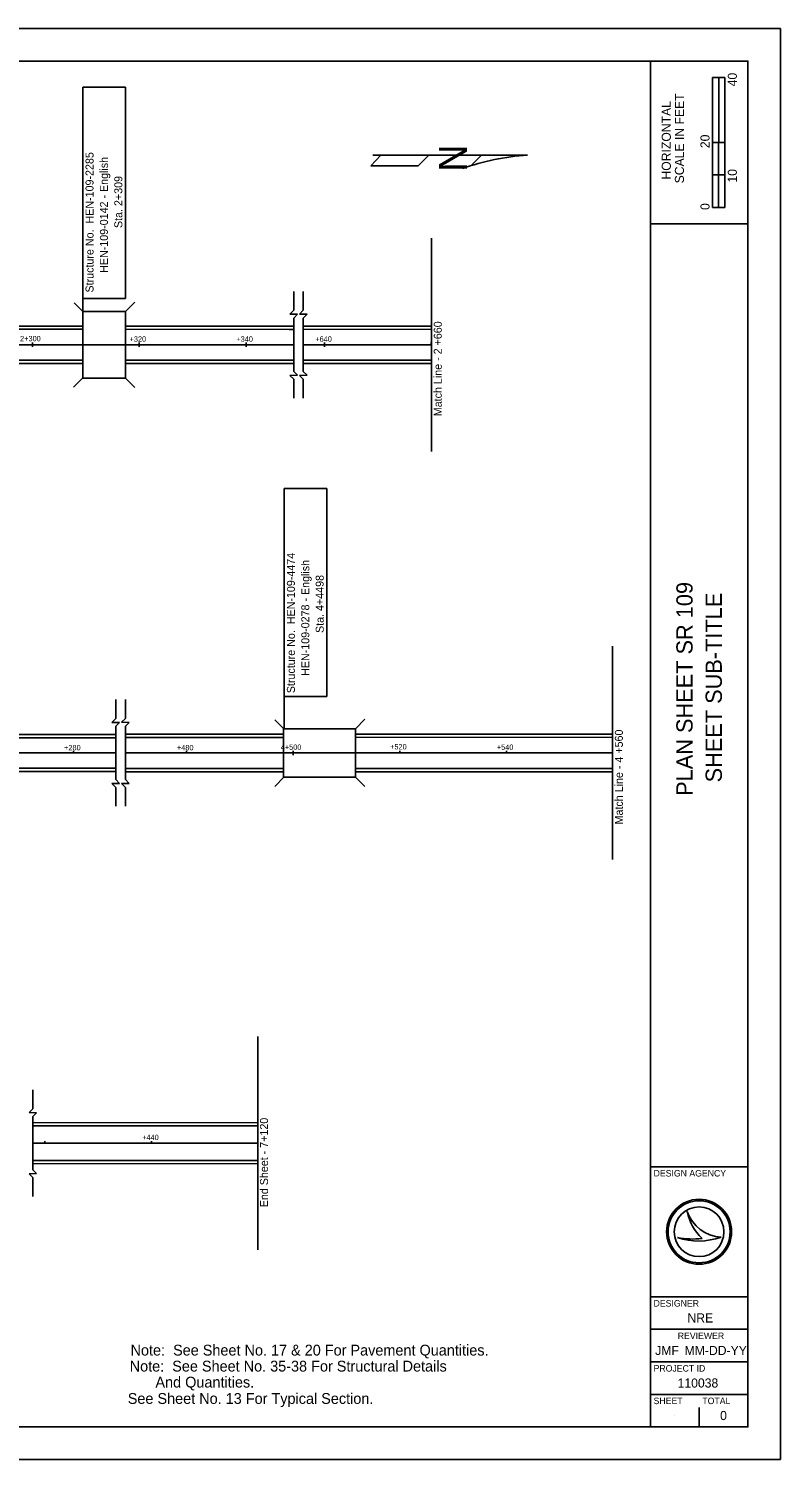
# Model space of a CAD drawing. Extents: x 3 to 683, y -6 to 434.
# Drawn here: x 451.7 to 682.9, y -6.3 to 433.7 of the extents above; entities that cross this region are included whole.
import ezdxf

# ---------------------------------------------------------------- set-up
doc = ezdxf.new("R2010")
doc.units = 0
for name, color, linetype in [('Default', 7, 'Continuous'), ('SH_Border', 7, 'Continuous'), ('SH_Cut_Line', 7, 'Continuous'), ('SH_Data', 7, 'Continuous')]:
    doc.layers.add(name, color=color, linetype=linetype)

msp = doc.modelspace()

# ---------------------------------------------------------------- linework, layer by layer
at = {"layer": 'Default'}
for p, q in [((468.32, 346.75), (468.32, 415.76)), ((468.32, 415.76), (481.45, 415.76)), ((481.48, 350.74), (481.43, 415.76)), ((559.96, 394.79), (556.87, 391.52)), ((557.56, 394.79), (605.01, 394.79)), ((574.75, 394.79), (571.48, 391.52)), ((590.91, 394.79), (587.65, 391.52)), ((571.48, 391.52), (556.87, 391.52)), ((575.55, 336.5), (575.55, 369.31)), ((533.22, 347.1), (533.22, 352.9)), ((536.13, 347.1), (536.13, 352.9)), ((465.67, 349.44), (468.57, 346.54)), ((468.34, 350.74), (481.46, 350.74)), ((481.45, 346.75), (484.35, 349.65)), ((468.32, 326.25), (468.32, 346.75)), ((481.45, 346.75), (468.32, 346.75)), ((481.45, 326.25), (481.45, 346.75)), ((532.03, 345.91), (533.22, 347.1)), ((532.03, 345.91), (534.38, 345.87)), ((533.22, 344.71), (534.38, 345.87)), ((533.22, 336.5), (533.22, 344.71)), ((534.95, 345.91), (536.13, 347.1)), ((534.95, 345.91), (537.29, 345.87)), ((536.13, 344.71), (537.29, 345.87)), ((536.13, 336.5), (536.13, 344.71)), ((468.32, 342.25), (414.87, 342.25)), ((468.32, 341.25), (414.87, 341.25)), ((532.92, 342.24), (481.45, 342.25)), ((532.92, 341.24), (481.45, 341.25)), ((533.22, 342.24), (531.8, 342.24)), ((533.22, 341.24), (531.8, 341.24)), ((575.55, 342.24), (536.13, 342.25)), ((575.55, 341.24), (536.13, 341.25)), ((532.92, 336.5), (414.87, 336.5)), ((452.9, 336.5), (452.9, 337.15)), ((452.9, 336.5), (452.9, 335.84)), ((485.71, 336.5), (485.71, 337.15)), ((485.71, 336.5), (485.71, 335.84)), ((518.52, 336.5), (518.52, 337.15)), ((518.52, 336.5), (518.52, 335.84)), ((533.22, 336.5), (531.8, 336.5)), ((533.22, 336.5), (533.22, 328.29)), ((575.55, 336.5), (536.13, 336.5)), ((536.13, 336.5), (536.13, 328.29)), ((542.71, 336.5), (542.71, 337.15)), ((542.71, 336.5), (542.71, 335.84)), ((575.52, 336.5), (575.52, 337.15)), ((575.55, 336.51), (575.55, 303.7)), ((468.32, 331.75), (414.87, 331.75)), ((468.32, 330.75), (414.87, 330.75)), ((532.92, 331.75), (481.45, 331.75)), ((532.92, 330.75), (481.45, 330.75)), ((533.22, 331.75), (531.8, 331.75)), ((533.22, 330.75), (531.8, 330.75)), ((575.55, 331.75), (536.13, 331.75)), ((575.55, 330.75), (536.13, 330.75)), ((465.49, 323.5), (468.39, 326.4)), ((481.45, 326.25), (468.32, 326.25)), ((481.45, 326.25), (484.35, 323.35)), ((532.03, 327.08), (534.38, 327.13)), ((532.03, 327.08), (533.22, 325.9)), ((533.22, 328.29), (534.38, 327.13)), ((533.22, 325.9), (533.22, 320.09)), ((534.95, 327.08), (537.29, 327.13)), ((534.95, 327.08), (536.13, 325.9)), ((536.13, 328.29), (537.29, 327.13)), ((536.13, 325.9), (536.13, 320.09)), ((530.27, 218.3), (530.27, 292.28)), ((530.27, 292.28), (543.39, 292.28)), ((543.42, 228.3), (543.38, 292.28)), ((631.27, 210.98), (631.27, 243.79)), ((478.49, 221.57), (478.49, 227.37)), ((481.43, 221.58), (481.43, 227.38)), ((530.28, 228.3), (543.41, 228.3)), ((477.3, 220.38), (478.49, 221.57)), ((477.3, 220.38), (479.65, 220.34)), ((478.49, 219.18), (479.65, 220.34)), ((480.24, 220.39), (481.43, 221.58)), ((480.24, 220.39), (482.59, 220.35)), ((481.43, 219.19), (482.59, 220.35)), ((527.37, 221.2), (530.27, 218.3)), ((552.19, 218.44), (555.09, 221.34)), ((478.49, 216.66), (414.65, 216.66)), ((478.49, 215.66), (414.65, 215.66)), ((478.49, 210.97), (478.49, 219.18)), ((481.43, 210.98), (481.43, 219.19)), ((530.05, 216.77), (481.43, 216.77)), ((530.05, 215.77), (481.43, 215.77)), ((530.05, 203.51), (530.05, 218.44)), ((552.19, 218.44), (530.05, 218.44)), ((552.19, 203.51), (552.19, 218.44)), ((631.27, 216.78), (552.19, 216.77)), ((631.27, 215.78), (552.19, 215.77)), ((465.5, 210.97), (465.5, 211.62)), ((500.19, 210.98), (500.19, 211.63)), ((533, 210.98), (533, 211.63)), ((565.81, 210.98), (565.81, 211.63)), ((598.62, 210.98), (598.62, 211.63)), ((478.49, 210.97), (329.03, 210.97)), ((478.49, 210.97), (478.49, 202.76)), ((631.27, 210.98), (481.43, 210.98)), ((481.43, 210.98), (481.43, 202.77)), ((533, 210.98), (533, 210.32)), ((631.27, 210.99), (631.27, 178.18)), ((478.49, 206.27), (414.65, 206.28)), ((478.49, 205.27), (414.65, 205.28)), ((478.49, 202.76), (479.65, 201.6)), ((530.05, 206.19), (481.43, 206.19)), ((530.05, 205.19), (481.43, 205.19)), ((481.43, 202.77), (482.59, 201.61)), ((527.37, 200.69), (530.27, 203.59)), ((552.19, 203.51), (530.05, 203.51)), ((631.27, 206.18), (552.19, 206.19)), ((631.27, 205.18), (552.19, 205.19)), ((552.19, 203.51), (555.09, 200.61)), ((477.3, 201.55), (479.65, 201.6)), ((477.3, 201.55), (478.49, 200.37)), ((478.49, 200.37), (478.49, 194.56)), ((480.24, 201.56), (482.59, 201.61)), ((480.24, 201.56), (481.43, 200.38)), ((481.43, 200.38), (481.43, 194.57)), ((522.12, 90.97), (522.12, 123.78)), ((452.97, 101.57), (452.97, 107.37)), ((451.78, 100.38), (452.97, 101.57)), ((451.78, 100.38), (454.13, 100.34)), ((452.97, 99.18), (454.13, 100.34)), ((452.97, 90.97), (452.97, 99.18)), ((522.12, 97.3), (452.97, 97.27)), ((522.12, 96.3), (452.97, 96.27)), ((452.97, 90.97), (452.97, 82.76)), ((522.12, 90.97), (452.97, 90.97)), ((456.66, 90.97), (456.66, 91.62)), ((489.47, 90.97), (489.47, 91.62)), ((522.12, 90.98), (522.12, 58.17)), ((522.12, 85.63), (452.97, 85.67)), ((522.12, 84.63), (452.97, 84.67)), ((451.78, 81.56), (454.13, 81.6)), ((451.78, 81.56), (452.97, 80.37)), ((452.97, 82.76), (454.13, 81.6)), ((452.97, 80.37), (452.97, 74.56))]:
    msp.add_line(p, q, dxfattribs=at)
msp.add_arc((609.29, 323.72), 71.19, 93.384, 109.8972, dxfattribs=at)
at = {"layer": 'SH_Border'}
for p, q in [((642.89, 3.72), (642.89, 423.72)), ((642.89, 373.72), (672.89, 373.72)), ((642.89, 83.72), (672.89, 83.72)), ((642.89, 43.72), (672.89, 43.72)), ((642.89, 33.72), (672.89, 33.72)), ((642.89, 23.72), (672.89, 23.72)), ((642.89, 13.72), (672.89, 13.72))]:
    msp.add_line(p, q, dxfattribs=at)
msp.add_lwpolyline([(32.89, 423.72), (672.89, 423.72), (672.89, 3.72), (32.89, 3.72)], close=True, dxfattribs=at)
at = {"layer": 'SH_Cut_Line'}
msp.add_lwpolyline([(2.89, -6.28), (682.89, -6.28), (682.89, 433.72), (2.89, 433.72)], close=True, dxfattribs=at)
at = {"layer": 'SH_Data'}
for p, q in [((662.02, 378.72), (662.02, 418.72)), ((665.77, 418.72), (662.02, 418.72)), ((662.02, 398.72), (662.02, 418.72)), ((662.02, 418.72), (663.89, 418.72)), ((663.89, 418.72), (663.91, 418.72)), ((663.91, 418.72), (663.91, 398.72)), ((665.77, 418.72), (665.77, 378.72)), ((663.91, 398.72), (662.02, 398.72)), ((665.76, 398.72), (663.89, 398.72)), ((663.89, 398.72), (663.89, 388.72)), ((665.76, 388.72), (665.76, 398.72)), ((663.89, 388.72), (662.02, 388.72)), ((662.02, 388.72), (662.02, 378.72)), ((663.89, 378.72), (663.89, 388.72)), ((663.89, 388.72), (665.76, 388.72)), ((665.77, 378.72), (662.02, 378.72)), ((662.02, 378.72), (663.89, 378.72)), ((654.24, 69.92), (654.24, 69.92)), ((651.23, 61.91), (651.23, 61.92)), ((657.89, 63.72), (657.89, 63.72)), ((664.64, 62.09), (664.64, 62.09)), ((657.89, 3.72), (657.89, 9.72)), ((650.39, 7.22), (650.39, 7.22))]:
    msp.add_line(p, q, dxfattribs=at)
for radius in [10, 9.54, 9.54, 7.64]:
    msp.add_circle((657.89, 63.72), radius, dxfattribs=at)
for centre, radius, start, end in [((665.21, 73.68), 11.6, 198.9257, 198.9319), ((669.82, 73.13), 15.91, 191.6379, 191.6421), ((665.21, 73.68), 11.6, 198.9319, 267.1657), ((669.82, 73.13), 15.91, 191.6421, 226.0947), ((657.68, 81.12), 20.26, 251.4576, 290.0832), ((657.68, 81.12), 20.26, 251.4527, 251.4576), ((655.85, 86.81), 25.32, 259.4964, 259.4995), ((655.85, 86.81), 25.32, 259.4995, 276.6672)]:
    msp.add_arc(centre, radius, start, end, dxfattribs=at)

# ---------------------------------------------------------------- texts
at = {"layer": 'Default'}
for s, height, rotation, p in [('N', 8.6, 270, (577.85, 398.06)), ('Structure No.  HEN-109-2285', 2.4606, 90, (471.62, 352.57)), ('HEN-109-0142 - English', 2.4606, 90, (476.05, 358.61)), ('Sta. 2+309', 2.461, 90, (480.48, 372.39)), ('Match Line - 2 +660', 2.4606, 90, (578.73, 314.53)), ('Structure No.  HEN-109-4474', 2.4606, 90, (533.56, 229.35)), ('HEN-109-0278 - English', 2.4606, 90, (537.99, 234.67)), ('Sta. 4+4498', 2.4606, 90, (542.42, 247.86)), ('Match Line - 4 +560', 2.4606, 90, (634.44, 188.99)), ('End Sheet - 7+120', 2.4606, 90, (525.29, 71.26))]:
    msp.add_text(s, height=height, rotation=rotation, dxfattribs=at).set_placement(p)
for s, height, p in [('2+300', 1.64, (449.03, 337.58)), ('+320', 1.64, (482.7, 337.44)), ('+340', 1.64, (515.54, 337.44)), ('+640', 1.64, (539.82, 337.44)), ('+280', 1.64, (462.56, 211.78)), ('+480', 1.64, (497.28, 211.79)), ('4+500', 1.64, (529.2, 211.93)), ('+520', 1.64, (562.84, 212.06)), ('+540', 1.64, (595.68, 211.93)), ('+440', 1.64, (486.58, 91.92)), ('Note:  See Sheet No. 17 & 20 For Pavement Quantities.', 3.3218, (483, 25.66)), ('Note:  See Sheet No. 35-38 For Structural Details', 3.3218, (482.74, 20.74)), ('      And Quantities.', 3.3218, (483.26, 15.82)), ('See Sheet No. 13 For Typical Section.', 3.3218, (482.15, 10.79))]:
    msp.add_text(s, height=height, dxfattribs=at).set_placement(p)
at = {"layer": 'SH_Data'}
for s, height, p in [('40', 2.8, (669.5, 415.97)), ('SCALE IN FEET', 2.8, (653.24, 386.14)), ('HORIZONTAL', 2.8, (649.19, 387.31)), ('20', 2.8, (661.1, 396.97)), ('10', 2.8, (669.5, 386.38)), ('0', 2.8, (661.1, 377.95)), ('PLAN SHEET SR 109', 5, (655.89, 197.78)), ('SHEET SUB-TITLE', 5, (664.89, 201.92))]:
    msp.add_text(s, height=height, rotation=90, dxfattribs=at).set_placement(p)
for s, height, p in [('DESIGN AGENCY', 2, (643.89, 80.72)), ('DESIGNER', 2, (643.89, 40.72)), ('NRE', 2.8, (654.31, 35.82)), ('REVIEWER', 2, (651.33, 30.72)), ('JMF', 2.8, (644.38, 25.82)), ('MM-DD-YY', 2.8, (653.44, 25.82)), ('PROJECT ID', 2, (643.89, 20.72)), ('110038', 2.8, (651.28, 15.82)), ('SHEET', 2, (643.89, 10.72)), ('TOTAL', 2, (658.89, 10.72)), ('0', 2.8, (664.35, 5.82))]:
    msp.add_text(s, height=height, dxfattribs=at).set_placement(p)

doc.saveas('drawing.dxf')
